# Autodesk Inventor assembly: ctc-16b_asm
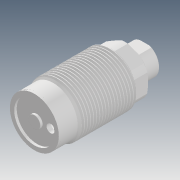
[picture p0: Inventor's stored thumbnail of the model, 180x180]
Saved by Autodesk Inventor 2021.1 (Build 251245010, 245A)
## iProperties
Created: 2018-08
Part Number: ctc-16b_asm
Description: STEP AP203
Document SubType Name: Assembly
Designer: user
Title: ctc-16b_asm.STEP
Revision Number: ÈÎºÎ
Sending System: SolidWorks 2015
Preprocessor: SwSTEP 2.0
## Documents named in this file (6)
- D:\Vault_2016\Projekty\Clamptek\Hydraulic\CTC\Inventor\ctc-16b\ctc-16b_asm.iam
- D:\Vault_2016\Projekty\Clamptek\Hydraulic\CTC\Inventor\ctc-16b\CTC-16ABT.ipt
- D:\Vault_2016\Projekty\Clamptek\Hydraulic\CTC\Inventor\ctc-16b\CTC-16BHSG.ipt
- D:\Vault_2016\Projekty\Clamptek\Hydraulic\CTC\Inventor\ctc-16b\CTC-16AHG.ipt
- D:\Vault_2016\Projekty\Clamptek\Hydraulic\CTC\Inventor\ctc-16b\CTC-16AMD.ipt
- D:\Vault_2016\Projekty\Clamptek\Hydraulic\CTC\Inventor\ctc-16b\CTC-16DP.ipt
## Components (5 placed, 5 different names)
1. CTC-16ABT_1
2. CTC-16BHSG_2
3. CTC-16AHG_3
4. CTC-16AMD_4
5. CTC-16DP_5
